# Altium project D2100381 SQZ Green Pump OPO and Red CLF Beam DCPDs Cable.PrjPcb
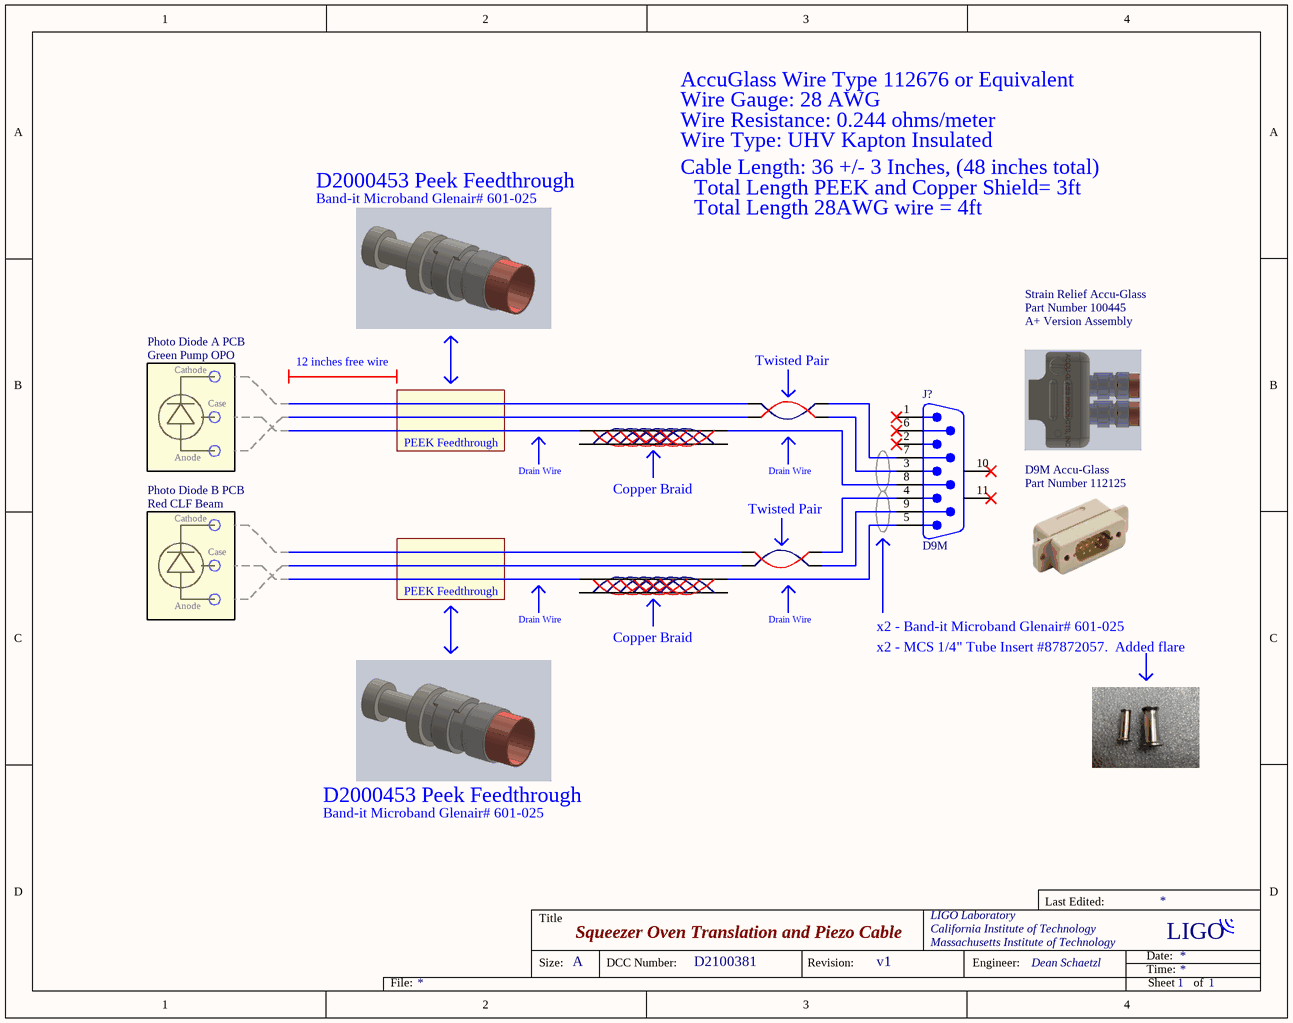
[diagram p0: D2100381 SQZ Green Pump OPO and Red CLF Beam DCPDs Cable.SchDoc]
1 sheet, 15 parts. Net scope: global (net labels, ports and power ports of the same name join across sheets).

## Sheet D2100381 SQZ Green Pump OPO and Red CLF Beam DCPDs Cable.SchDoc: Squeezer Oven Translation and Piezo Cable
size A; Organization: LIGO Laboratory; Address1: California Institute of Technology; Address2: Massachusetts Institute of Technology; DocumentNumber: D2100381; Revision: v1; SheetNumber: 1; SheetTotal: 1; Engineer: Dean Schaetzl

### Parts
(Parts that share a designator on the sheet are numbered #1, #2 ... from top to bottom, then left to right.)
J?  D9M  [D9M]
TW1  Twisted Pair  (value not drawn)
TW?#1  Twisted Pair  (value not drawn)
TW?#2  Twisted Pair  (value not drawn)
TW?#3  Twisted Pair  (value not drawn)
TW?#4  Twisted Pair  (value not drawn)
TW?#5  Twisted Pair  (value not drawn)
TW?#6  Twisted Pair  (value not drawn)
TW?#7  Twisted Pair  (value not drawn)
TW?#8  Twisted Pair  (value not drawn)
TW?#9  Twisted Pair  (value not drawn)
TW?#10  Twisted Pair  (value not drawn)
TW?#11  Twisted Pair  (value not drawn)
TW?#12  Twisted Pair  (value not drawn)
TW?#13  Twisted Pair  (value not drawn)

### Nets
NetJ?_3: J?.3 TW1.2A
NetJ?_4: J?.4 TW?#7.2A
NetJ?_5: J?.5 TW?#13.2A
NetJ?_7: J?.7 TW1.1A
NetJ?_8: J?.8 TW?#6.2A
NetJ?_9: J?.9 TW?#7.1A

Not connected (* = marked no-connect by the designer): J? 1* 2* 6* 10(MH1)* 11(MH2)*; TW1 1B 2B; TW?#1 1A 1B 2A 2B; TW?#2 1A 1B 2A 2B; TW?#3 1A 1B 2A 2B; TW?#4 1A 1B 2A 2B; TW?#5 1A 1B 2A 2B; TW?#6 1A 1B 2B; TW?#7 1B 2B; TW?#8 1A 1B 2A 2B; TW?#9 1A 1B 2A 2B; TW?#10 1A 1B 2A 2B; TW?#11 1A 1B 2A 2B; TW?#12 1A 1B 2A 2B; TW?#13 1A 1B 2B

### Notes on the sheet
- AccuGlass Wire Type 112676 or Equivalent
- Wire Gauge: 28 AWG
- Wire Type: UHV Kapton Insulated
- Wire Resistance: 0.244 ohms/meter
- D2000453 Peek Feedthrough
- Band-it Microband Glenair# 601-025
- Cable Length: 36 +/- 3 Inches, (48 inches total)
- Total Length PEEK and Copper Shield= 3ft
- Total Length 28AWG wire = 4ft
- Strain Relief Accu-Glass
- Photo Diode A PCB
- Green Pump OPO
- Cathode
- 12 inches free wire
- (near TW1) Twisted Pair
- Part Number 100445
- A+ Version Assembly
- Case
- Photo Diode B PCB
- Red CLF Beam
- Anode
- PEEK Feedthrough
- (near TW?#1) Drain Wire
- (near TW?#1) Copper Braid
- Drain Wire
- D9M Accu-Glass
- Part Number 112125
- (near TW?#7) Twisted Pair
- (near TW?#8) Drain Wire
- (near TW?#8) Copper Braid
- (near TW?#7) Drain Wire
- x2 - Band-it Microband Glenair# 601-025
- x2 - MCS 1/4" Tube Insert #87872057.  Added flare

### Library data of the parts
J? = D9M: DB9M; Manufacturer: TE Connectivity; Manufacturer Part Number: 5747871-2; Plating: Tin; Body Material: Metal,Steel; Gender: Male; Voltage Rating: 125V; Connector Type: Plug; Number of Positions: 9; Number of Ports: 1; Max Supply Voltage (AC): 250V; Mating Connector Lock: No (Without); Current Rating: 6A; Preloaded: Yes; Max Voltage Rating (DC): 250.25kV; PCB Mount Retention: With; PCB Mounting Orientation: Vertical; Pitch: 0.108inch; PCB Thickness: 2.36mm; Contact Post Length: 0.125inch; Hole Diameter: 0.12inch; Approvals: UL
